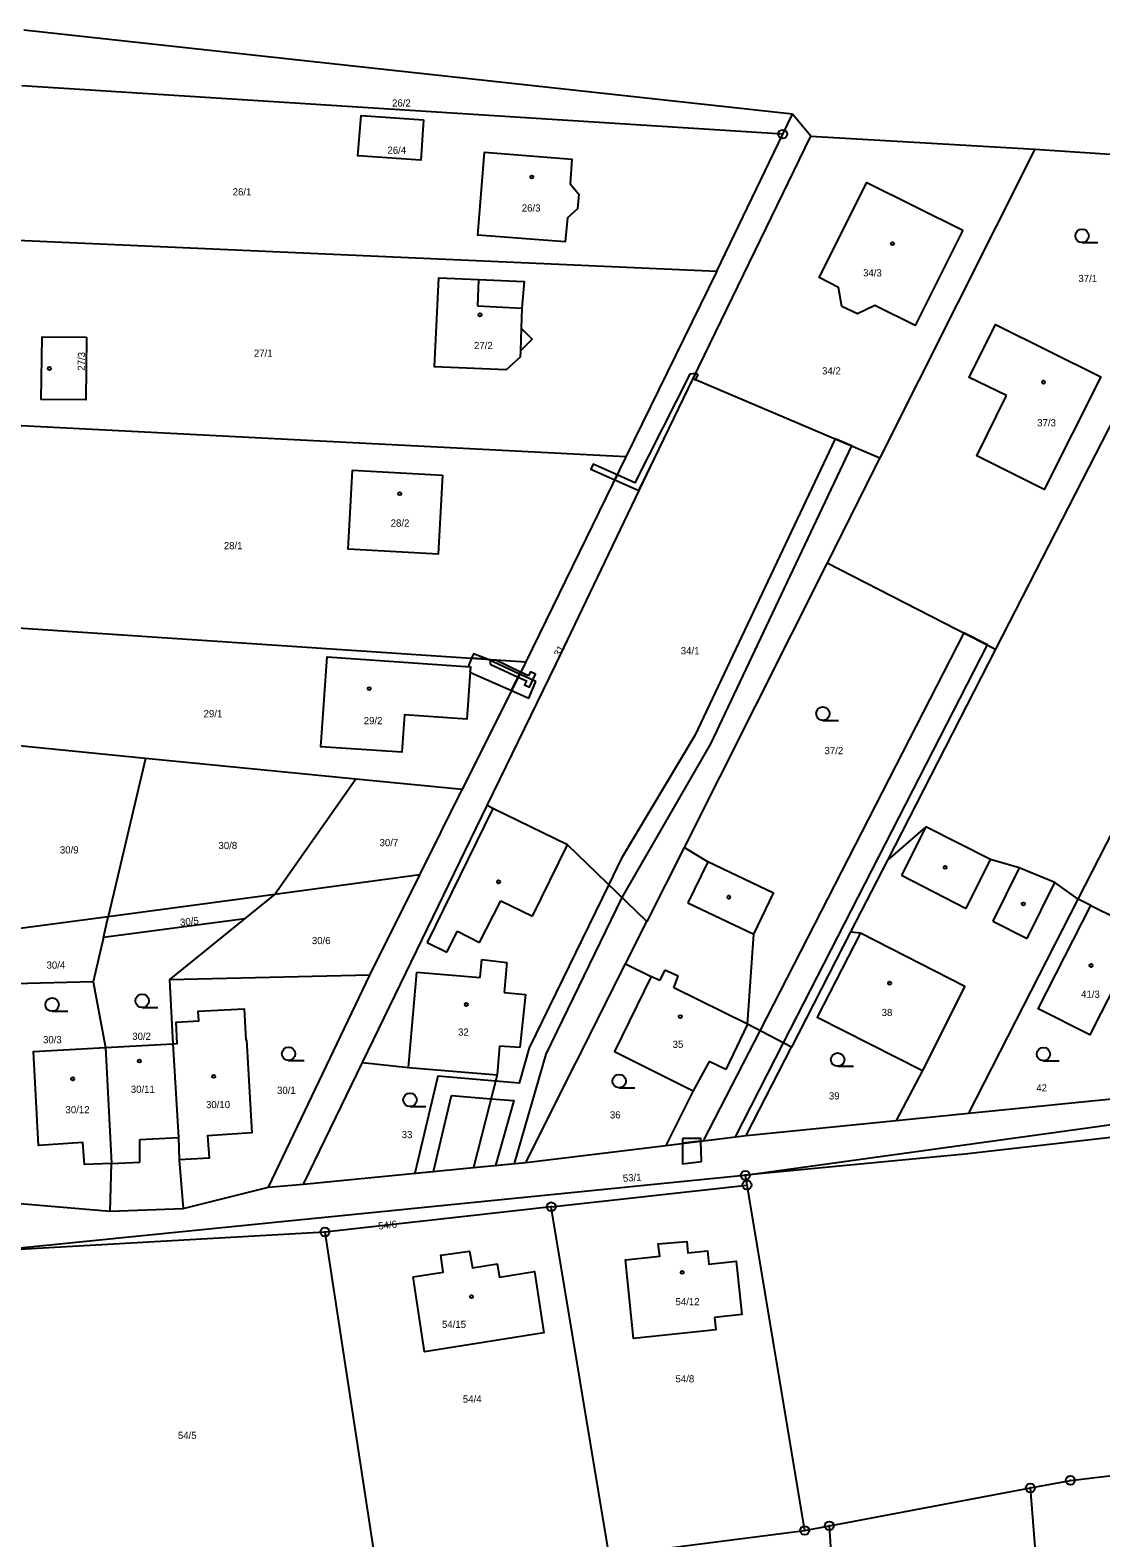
# Model space of a CAD drawing. Extents: x -587171 to -555306, y -1167727 to -1074732.
# Drawn here: x -559609.3 to -559489.7, y -1076445.1 to -1076276.8 of the extents above; entities that cross this region are included whole.
import ezdxf

# ---------------------------------------------------------------- set-up
doc = ezdxf.new("R2010")
doc.units = 0
for name, color, linetype in [('Hranice parcel', 7, 'Continuous'), ('Parcelní čísla', 7, 'Continuous'), ('Vnitřní kresba', 7, 'Continuous'), ('Věcná břemena k části', 7, 'Continuous'), ('Značky bodu BP', 7, 'Continuous'), ('Značky budov', 7, 'Continuous'), ('Značky kultur', 7, 'Continuous')]:
    doc.layers.add(name, color=color, linetype=linetype)

msp = doc.modelspace()

# ---------------------------------------------------------------- linework, layer by layer
at = {"layer": 'Hranice parcel'}
for p, q in [((-559524.17, -1076286.21), (-559609.99, -1076276.84)), ((-559525.24, -1076288.45), (-559610.23, -1076283.04)), ((-559525.24, -1076288.45), (-559524.17, -1076286.21)), ((-559522.12, -1076288.66), (-559524.17, -1076286.21)), ((-559535.26, -1076315.74), (-559522.12, -1076288.66)), ((-559532.59, -1076303.73), (-559525.24, -1076288.45)), ((-559522.12, -1076288.66), (-559497.1, -1076290.11)), ((-559497.1, -1076290.11), (-559514.41, -1076324.57)), ((-559497.1, -1076290.11), (-559473.66, -1076291.66)), ((-559473.66, -1076291.66), (-559501.48, -1076345.93)), ((-559610.75, -1076300.3), (-559532.59, -1076303.73)), ((-559532.59, -1076303.73), (-559542.75, -1076324.48)), ((-559535.26, -1076315.74), (-559514.41, -1076324.57)), ((-559542.75, -1076324.48), (-559611.03, -1076320.97)), ((-559542.75, -1076324.48), (-559553.95, -1076347.35)), ((-559514.41, -1076324.57), (-559520.3, -1076336.3)), ((-559520.3, -1076336.3), (-559536.25, -1076368.06)), ((-559520.3, -1076336.3), (-559501.48, -1076345.93)), ((-559611.22, -1076343.53), (-559553.95, -1076347.35)), ((-559501.48, -1076345.93), (-559513.56, -1076369.48)), ((-559553.95, -1076347.35), (-559561.03, -1076361.61)), ((-559596.39, -1076358.13), (-559611.68, -1076356.63)), ((-559596.39, -1076358.13), (-559600.56, -1076375.8)), ((-559572.92, -1076360.44), (-559596.39, -1076358.13)), ((-559572.92, -1076360.44), (-559581.96, -1076373.31)), ((-559561.03, -1076361.61), (-559572.92, -1076360.44)), ((-559565.78, -1076371.13), (-559561.03, -1076361.61)), ((-559492.25, -1076373.84), (-559485.29, -1076360.22)), ((-559572.18, -1076392.08), (-559558.25, -1076363.4)), ((-559536.25, -1076368.06), (-559540.41, -1076376.33)), ((-559513.56, -1076369.48), (-559517.66, -1076377.49)), ((-559565.78, -1076371.13), (-559581.96, -1076373.31)), ((-559571.36, -1076382.31), (-559565.78, -1076371.13)), ((-559581.96, -1076373.31), (-559600.56, -1076375.8)), ((-559585.3, -1076376.02), (-559581.96, -1076373.31)), ((-559504.45, -1076397.71), (-559492.25, -1076373.84)), ((-559490.85, -1076374.55), (-559492.25, -1076373.84)), ((-559600.56, -1076375.8), (-559612.37, -1076377.39)), ((-559601.11, -1076378.13), (-559600.56, -1076375.8)), ((-559585.3, -1076376.02), (-559601.11, -1076378.13)), ((-559593.72, -1076382.86), (-559585.3, -1076376.02)), ((-559542.79, -1076381.06), (-559540.41, -1076376.33)), ((-559601.11, -1076378.13), (-559602.27, -1076383.08)), ((-559517.66, -1076377.49), (-559524.25, -1076390.35)), ((-559553.92, -1076403.22), (-559542.79, -1076381.06)), ((-559602.27, -1076383.08), (-559612.51, -1076383.33)), ((-559602.27, -1076383.08), (-559600.86, -1076390.4)), ((-559571.36, -1076382.31), (-559593.72, -1076382.86)), ((-559593.72, -1076382.86), (-559593.36, -1076389.99)), ((-559582.66, -1076405.97), (-559571.36, -1076382.31)), ((-559600.86, -1076390.4), (-559593.36, -1076389.99)), ((-559529.32, -1076400.22), (-559524.25, -1076390.35)), ((-559600.86, -1076390.4), (-559600.22, -1076403.36)), ((-559578.78, -1076405.66), (-559572.18, -1076392.08)), ((-559504.45, -1076397.71), (-559485.06, -1076395.8)), ((-559529.32, -1076400.22), (-559512.58, -1076398.53)), ((-559512.58, -1076398.53), (-559504.45, -1076397.71)), ((-559538.3, -1076401.32), (-559529.32, -1076400.22)), ((-559553.92, -1076403.22), (-559538.3, -1076401.32)), ((-559600.35, -1076408.67), (-559600.22, -1076403.36)), ((-559592.63, -1076402.93), (-559592.2, -1076408.38)), ((-559578.78, -1076405.66), (-559559.79, -1076403.8)), ((-559559.79, -1076403.8), (-559553.92, -1076403.22)), ((-559529.43, -1076404.66), (-559529.24, -1076405.75)), ((-559592.2, -1076408.38), (-559582.66, -1076405.97)), ((-559582.66, -1076405.97), (-559578.78, -1076405.66)), ((-559551.1, -1076408.18), (-559529.24, -1076405.75)), ((-559529.24, -1076405.75), (-559522.8, -1076444.31)), ((-559613.69, -1076407.52), (-559600.35, -1076408.67)), ((-559600.35, -1076408.67), (-559592.2, -1076408.38)), ((-559551.1, -1076408.18), (-559576.38, -1076411)), ((-559544.62, -1076447.11), (-559551.1, -1076408.18)), ((-559576.38, -1076411), (-559614.16, -1076413.16)), ((-559576.38, -1076411), (-559570.34, -1076450.42)), ((-559520.04, -1076443.79), (-559497.59, -1076439.56)), ((-559495.36, -1076466.98), (-559497.59, -1076439.56)), ((-559522.8, -1076444.31), (-559520.04, -1076443.79)), ((-559518.06, -1076471.56), (-559520.04, -1076443.79)), ((-559543.14, -1076446.92), (-559522.8, -1076444.31))]:
    msp.add_line(p, q, dxfattribs=at)
for points in [[(-559565.37, -1076286.85), (-559565.67, -1076291.34), (-559572.68, -1076290.86), (-559572.31, -1076286.35), (-559565.37, -1076286.85)], [(-559548.02, -1076295.16), (-559548.16, -1076296.8), (-559549.29, -1076297.79), (-559549.53, -1076300.48), (-559559.3, -1076299.72), (-559558.54, -1076290.46), (-559548.78, -1076291.24), (-559549, -1076294), (-559548.02, -1076295.16)], [(-559505.12, -1076299.18), (-559510.47, -1076309.82), (-559514.97, -1076307.58), (-559516.9, -1076308.52), (-559518.63, -1076307.7), (-559519.01, -1076305.56), (-559521.19, -1076304.44), (-559515.84, -1076293.83), (-559505.12, -1076299.18)], [(-559554.57, -1076313.34), (-559556.14, -1076314.77), (-559564.12, -1076314.42), (-559563.65, -1076304.47), (-559559.21, -1076304.67), (-559554.13, -1076304.88), (-559554.37, -1076307.87), (-559554.45, -1076310.12), (-559553.23, -1076311.33), (-559554.54, -1076312.63), (-559554.57, -1076313.34)], [(-559602.98, -1076311.1), (-559603.06, -1076318.11), (-559608.06, -1076318.05), (-559607.94, -1076311.06), (-559602.98, -1076311.1)], [(-559500.24, -1076317.61), (-559504.42, -1076315.61), (-559501.49, -1076309.68), (-559489.73, -1076315.54), (-559496.05, -1076328.11), (-559503.58, -1076324.35), (-559500.24, -1076317.61)], [(-559558.25, -1076363.4), (-559557.54, -1076361.95), (-559550.56, -1076347.58), (-559539.58, -1076324.64), (-559535.26, -1076315.74)], [(-559563.24, -1076326.53), (-559563.71, -1076335.33), (-559573.78, -1076334.78), (-559573.28, -1076325.97), (-559563.24, -1076326.53)], [(-559560.13, -1076347.9), (-559560.52, -1076353.74), (-559567.48, -1076353.28), (-559567.77, -1076357.43), (-559576.81, -1076356.82), (-559576.11, -1076346.81), (-559560.13, -1076347.9)], [(-559540.41, -1076376.33), (-559549.3, -1076367.76), (-559557.61, -1076363.71), (-559558.25, -1076363.4)], [(-559492.25, -1076373.84), (-559494.86, -1076371.98), (-559498.85, -1076370.34), (-559502.04, -1076369.4), (-559509.26, -1076365.75), (-559513.56, -1076369.48)], [(-559524.25, -1076390.35), (-559529.19, -1076387.81), (-559528.46, -1076377.73), (-559526.28, -1076373.16), (-559533.6, -1076369.68), (-559536.25, -1076368.06)], [(-559489.71, -1076386.58), (-559490.94, -1076388.99), (-559496.72, -1076386.07), (-559490.85, -1076374.55)], [(-559490.85, -1076374.55), (-559485.02, -1076377.43), (-559489.71, -1076386.58)], [(-559517.66, -1076377.49), (-559516.57, -1076377.6), (-559521.41, -1076387.01), (-559509.64, -1076392.98), (-559512.58, -1076398.53)], [(-559542.79, -1076381.06), (-559539.94, -1076382.46), (-559544.03, -1076390.84), (-559535.24, -1076395.24), (-559538.3, -1076401.32)], [(-559593.36, -1076389.99), (-559592.87, -1076389.96), (-559593, -1076387.56), (-559590.46, -1076387.42), (-559590.52, -1076386.36), (-559585.38, -1076386.09), (-559585.19, -1076389.53), (-559585.12, -1076389.53)], [(-559593.36, -1076389.99), (-559592.72, -1076400.43), (-559592.63, -1076402.93)], [(-559585.12, -1076389.53), (-559584.54, -1076399.92), (-559589.47, -1076400.24), (-559589.29, -1076402.77), (-559592.63, -1076402.93)], [(-559600.22, -1076403.36), (-559603.22, -1076403.47), (-559603.39, -1076401), (-559608.36, -1076401.33), (-559608.9, -1076390.85), (-559600.86, -1076390.4)], [(-559572.18, -1076392.08), (-559567.03, -1076392.64), (-559557.15, -1076393.46), (-559559.79, -1076403.8)], [(-559529.43, -1076404.66), (-559482.86, -1076398.2), (-559441.57, -1076396.27), (-559435.57, -1076398.37), (-559414.99, -1076406.03), (-559382.52, -1076424.05), (-559352.65, -1076443.99)], [(-559441.99, -1076400.6), (-559453.4, -1076398.3), (-559474.91, -1076398.9), (-559504.91, -1076402.3), (-559529.43, -1076404.66)], [(-559529.43, -1076404.66), (-559529.56, -1076404.67), (-559580.1, -1076409.76), (-559614.16, -1076413.16)], [(-559532.86, -1076420.53), (-559532.71, -1076421.93), (-559541.92, -1076422.87), (-559542.82, -1076414.09), (-559538.98, -1076413.69), (-559539.14, -1076412.33), (-559535.97, -1076412.05), (-559535.83, -1076413.33), (-559533.65, -1076413.1), (-559533.48, -1076414.57), (-559530.46, -1076414.25), (-559529.82, -1076420.21), (-559532.86, -1076420.53)], [(-559566.51, -1076415.98), (-559563.16, -1076415.47), (-559563.43, -1076413.59), (-559560.21, -1076413.14), (-559559.9, -1076414.99), (-559557.13, -1076414.56), (-559556.88, -1076416.03), (-559552.96, -1076415.42), (-559551.92, -1076422.23), (-559565.24, -1076424.37), (-559566.51, -1076415.98)], [(-559497.59, -1076439.56), (-559493.12, -1076438.72), (-559489.72, -1076438.34), (-559474.75, -1076436.61)]]:
    msp.add_lwpolyline(points, dxfattribs=at)
at = {"layer": 'Vnitřní kresba'}
for p, q in [((-559559.21, -1076304.67), (-559559.34, -1076307.63)), ((-559559.34, -1076307.63), (-559554.37, -1076307.87)), ((-559554.45, -1076310.12), (-559554.54, -1076312.63)), ((-559557.61, -1076363.71), (-559564.94, -1076378.67)), ((-559509.26, -1076365.75), (-559511.98, -1076371.17)), ((-559553.18, -1076375.75), (-559549.3, -1076367.76)), ((-559533.6, -1076369.68), (-559535.86, -1076374.25)), ((-559504.78, -1076374.87), (-559502.04, -1076369.4)), ((-559511.98, -1076371.17), (-559504.78, -1076374.87)), ((-559498.85, -1076370.34), (-559501.79, -1076376.29)), ((-559497.94, -1076378.24), (-559494.86, -1076371.98)), ((-559559.1, -1076378.68), (-559556.74, -1076374.04)), ((-559556.74, -1076374.04), (-559553.18, -1076375.75)), ((-559535.86, -1076374.25), (-559528.46, -1076377.73)), ((-559501.79, -1076376.29), (-559497.94, -1076378.24)), ((-559562.74, -1076379.75), (-559561.58, -1076377.41)), ((-559561.58, -1076377.41), (-559559.1, -1076378.68)), ((-559516.57, -1076377.6), (-559504.9, -1076383.57)), ((-559564.94, -1076378.67), (-559562.74, -1076379.75)), ((-559559.03, -1076382.59), (-559558.84, -1076380.59)), ((-559558.84, -1076380.59), (-559556.06, -1076380.91)), ((-559556.06, -1076380.91), (-559556.35, -1076384.27)), ((-559538.41, -1076381.76), (-559538.99, -1076382.93)), ((-559536.91, -1076382.45), (-559538.41, -1076381.76)), ((-559567.03, -1076392.64), (-559566.09, -1076381.99)), ((-559566.09, -1076381.99), (-559559.03, -1076382.59)), ((-559538.99, -1076382.93), (-559539.94, -1076382.46)), ((-559537.41, -1076383.72), (-559536.91, -1076382.45)), ((-559504.9, -1076383.57), (-559509.64, -1076392.98)), ((-559556.35, -1076384.27), (-559553.98, -1076384.48)), ((-559553.98, -1076384.48), (-559554.59, -1076390.4)), ((-559529.19, -1076387.81), (-559537.41, -1076383.72)), ((-559529.19, -1076387.81), (-559531.6, -1076392.84)), ((-559556.87, -1076390.26), (-559557.15, -1076393.46)), ((-559554.59, -1076390.4), (-559556.87, -1076390.26)), ((-559533.45, -1076391.96), (-559535.24, -1076395.24)), ((-559531.6, -1076392.84), (-559533.45, -1076391.96)), ((-559597.04, -1076400.65), (-559592.72, -1076400.43)), ((-559597.03, -1076403.2), (-559597.04, -1076400.65)), ((-559600.22, -1076403.36), (-559597.03, -1076403.2))]:
    msp.add_line(p, q, dxfattribs=at)
at = {"layer": 'Věcná břemena k části'}
for points in [[(-559543.73, -1076326.49), (-559544, -1076327.03), (-559541.3, -1076328.23), (-559539.58, -1076324.64), (-559535.26, -1076315.74), (-559534.99, -1076315.18), (-559535.61, -1076315.23), (-559541.77, -1076327.36)], [(-559534.7, -1076315.31), (-559534.99, -1076315.18), (-559535.26, -1076315.74), (-559534.97, -1076315.86)], [(-559557.83, -1076396.12), (-559555.26, -1076396.33), (-559557.34, -1076403.56), (-559555.2, -1076403.35), (-559551.68, -1076391.14), (-559543.17, -1076373.67), (-559533.29, -1076356.51), (-559517.54, -1076323.24), (-559519.39, -1076322.46), (-559535.06, -1076355.57), (-559543.29, -1076369.35), (-559544.68, -1076372.21), (-559553.56, -1076390.42), (-559554.69, -1076394.37), (-559557.33, -1076394.15), (-559563.77, -1076393.61), (-559566.34, -1076404.44), (-559564.23, -1076404.23), (-559562.22, -1076395.75)], [(-559543.73, -1076326.49), (-559546.42, -1076325.29), (-559546.66, -1076325.84), (-559544, -1076327.03)], [(-559527.81, -1076388.52), (-559534.12, -1076400.81), (-559530.52, -1076400.37), (-559525.15, -1076389.89), (-559502.37, -1076345.47), (-559505.04, -1076344.1)], [(-559559.99, -1076346.95), (-559558.21, -1076347.07), (-559559.79, -1076346.46)], [(-559560.17, -1076348.51), (-559555.54, -1076350.56), (-559554.63, -1076348.71), (-559558.21, -1076347.07), (-559559.99, -1076346.95), (-559560.36, -1076347.88), (-559560.13, -1076347.9)], [(-559557.9, -1076347.6), (-559554.79, -1076349.05), (-559554.52, -1076348.5), (-559557.29, -1076347.17), (-559557.91, -1076347.19)], [(-559552.8, -1076349.55), (-559554.63, -1076348.71), (-559555.54, -1076350.56), (-559553.61, -1076351.42)], [(-559553.62, -1076348.93), (-559554.52, -1076348.5), (-559554.79, -1076349.05), (-559553.87, -1076349.48), (-559554.07, -1076349.93), (-559553.53, -1076350.18), (-559552.87, -1076348.73), (-559553.41, -1076348.48)], [(-559536.44, -1076400.57), (-559536.44, -1076401.09), (-559534.39, -1076400.84), (-559534.4, -1076400.57)], [(-559534.3, -1076403.12), (-559534.39, -1076400.84), (-559536.44, -1076401.09), (-559536.43, -1076403.38)]]:
    msp.add_lwpolyline(points, close=True, dxfattribs=at)
at = {"layer": 'Značky bodu BP'}
for centre, radius in [((-559525.24, -1076288.45), 0.5), ((-559525.24, -1076288.45), 0.0303), ((-559529.43, -1076404.66), 0.5), ((-559529.24, -1076405.75), 0.5), ((-559529.43, -1076404.66), 0.0303), ((-559529.24, -1076405.75), 0.0303), ((-559551.1, -1076408.18), 0.5), ((-559551.1, -1076408.18), 0.0303), ((-559576.38, -1076411), 0.5), ((-559576.38, -1076411), 0.0303), ((-559497.59, -1076439.56), 0.5), ((-559493.12, -1076438.72), 0.5), ((-559493.12, -1076438.72), 0.0303), ((-559497.59, -1076439.56), 0.0303), ((-559522.8, -1076444.31), 0.5), ((-559520.04, -1076443.79), 0.5), ((-559520.04, -1076443.79), 0.0303), ((-559522.8, -1076444.31), 0.0303)]:
    msp.add_circle(centre, radius, dxfattribs=at)
at = {"layer": 'Značky budov'}
for centre in [(-559553.27, -1076293.24), (-559512.99, -1076300.67), (-559559.06, -1076308.61), (-559607.14, -1076314.6), (-559496.12, -1076316.13), (-559568.02, -1076328.58), (-559571.43, -1076350.35), (-559507.11, -1076370.28), (-559556.97, -1076371.91), (-559531.27, -1076373.62), (-559498.38, -1076374.37), (-559490.82, -1076381.24), (-559513.31, -1076383.22), (-559560.59, -1076385.6), (-559536.69, -1076386.95), (-559597.09, -1076391.91), (-559604.53, -1076393.9), (-559588.79, -1076393.62), (-559536.47, -1076415.49), (-559560, -1076418.21)]:
    msp.add_circle(centre, 0.175, dxfattribs=at)
at = {"layer": 'Značky kultur'}
for p, q in [((-559491.82, -1076300.55), (-559490.07, -1076300.55)), ((-559520.76, -1076353.88), (-559519.01, -1076353.88)), ((-559606.84, -1076386.36), (-559605.09, -1076386.36)), ((-559596.78, -1076385.94), (-559595.03, -1076385.94)), ((-559580.43, -1076391.85), (-559578.68, -1076391.85)), ((-559496.13, -1076391.89), (-559494.38, -1076391.89)), ((-559519.11, -1076392.5), (-559517.36, -1076392.5)), ((-559543.51, -1076394.9), (-559541.76, -1076394.9)), ((-559566.87, -1076396.99), (-559565.12, -1076396.99))]:
    msp.add_line(p, q, dxfattribs=at)
for centre in [(-559491.82, -1076299.8), (-559520.76, -1076353.13), (-559606.84, -1076385.61), (-559596.78, -1076385.19), (-559580.43, -1076391.1), (-559519.11, -1076391.75), (-559496.13, -1076391.14), (-559543.51, -1076394.15), (-559566.87, -1076396.24)]:
    msp.add_circle(centre, 0.75, dxfattribs=at)

# ---------------------------------------------------------------- texts
at = {"layer": 'Parcelní čísla'}
for s, p in [('26/2', (-559568.87, -1076285.37)), ('26/4', (-559569.39, -1076290.64)), ('26/1', (-559586.67, -1076295.29)), ('26/3', (-559554.39, -1076297.09)), ('34/3', (-559516.27, -1076304.33)), ('37/1', (-559492.23, -1076304.96)), ('27/1', (-559584.3, -1076313.3)), ('27/2', (-559559.72, -1076312.44)), ('34/2', (-559520.85, -1076315.27)), ('37/3', (-559496.83, -1076321.06)), ('28/2', (-559569.03, -1076332.26)), ('28/1', (-559587.66, -1076334.78)), ('34/1', (-559536.63, -1076346.51)), ('29/1', (-559589.92, -1076353.54)), ('29/2', (-559572.04, -1076354.32)), ('37/2', (-559520.58, -1076357.66)), ('30/9', (-559605.97, -1076368.74)), ('30/8', (-559588.26, -1076368.25)), ('30/7', (-559570.27, -1076367.93)), ('30/6', (-559577.83, -1076378.86)), ('30/4', (-559607.46, -1076381.6)), ('41/3', (-559491.93, -1076384.85)), ('38', (-559514.2, -1076386.89)), ('32', (-559561.5, -1076389.08)), ('30/3', (-559607.85, -1076389.93)), ('30/2', (-559597.89, -1076389.55)), ('35', (-559537.54, -1076390.44)), ('30/11', (-559598.05, -1076395.46)), ('30/1', (-559581.72, -1076395.58)), ('39', (-559520.09, -1076396.2)), ('42', (-559496.93, -1076395.31)), ('30/12', (-559605.34, -1076397.74)), ('30/10', (-559589.65, -1076397.17)), ('36', (-559544.55, -1076398.32)), ('33', (-559567.8, -1076400.52)), ('54/12', (-559537.22, -1076419.17)), ('54/15', (-559563.3, -1076421.7)), ('54/8', (-559537.22, -1076427.78)), ('54/4', (-559560.97, -1076430.04)), ('54/5', (-559592.79, -1076434.1))]:
    msp.add_text(s, height=0.803, dxfattribs=at).set_placement(p)
for s, rotation, p in [('27/3', 89, (-559603.19, -1076314.86)), ('31', 59, (-559550.18, -1076346.85)), ('30/5', 6, (-559592.5, -1076376.84)), ('53/1', 4, (-559543.07, -1076405.4)), ('54/6', 6, (-559570.37, -1076410.72))]:
    msp.add_text(s, height=0.803, rotation=rotation, dxfattribs=at).set_placement(p)

doc.saveas('drawing.dxf')
